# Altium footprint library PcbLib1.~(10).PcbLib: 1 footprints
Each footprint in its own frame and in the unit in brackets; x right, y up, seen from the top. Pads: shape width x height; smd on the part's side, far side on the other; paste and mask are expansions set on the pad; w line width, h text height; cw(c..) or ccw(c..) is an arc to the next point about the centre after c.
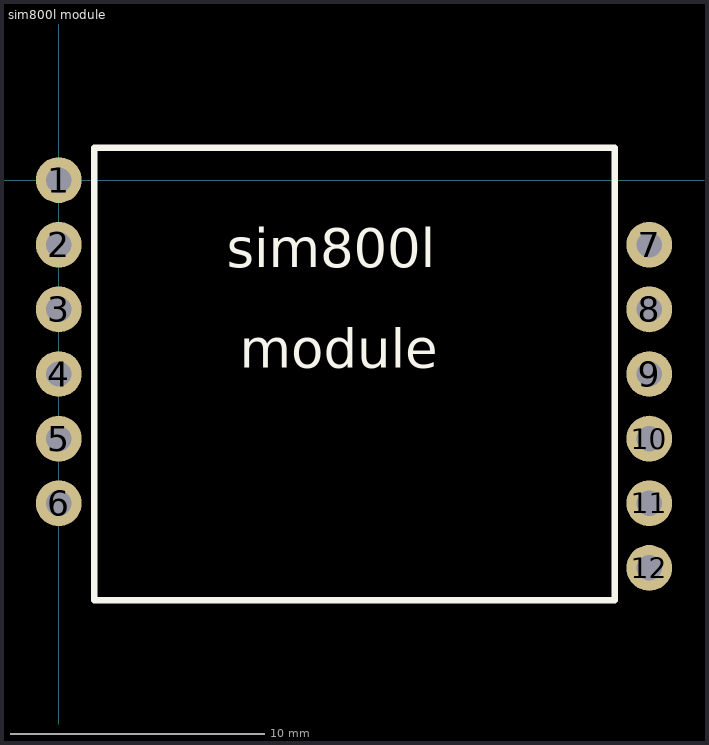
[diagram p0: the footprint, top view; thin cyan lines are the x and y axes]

## sim800l module [mm]
height 10
pads (12):
  round 1.8 hole 1: 1(0,0) 2(0,-2.54) 3(0,-5.08) 4(0,-7.62) 5(0,-10.16) 6(0,-12.7) 7(23.2,-2.54) 8(23.2,-5.08) 9(23.2,-7.62) 10(23.2,-10.16) 11(23.2,-12.7) 12(23.2,-15.24)
Top Overlay:
  lines w0.254: 1.397,-16.51 1.397,1.27 19.939,1.27 21.844,1.27 21.844,-16.51 1.397,-16.51
  text "sim800l" at 6.604,-3.429 h1.52
  text "module" at 7.112,-7.366 h1.52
